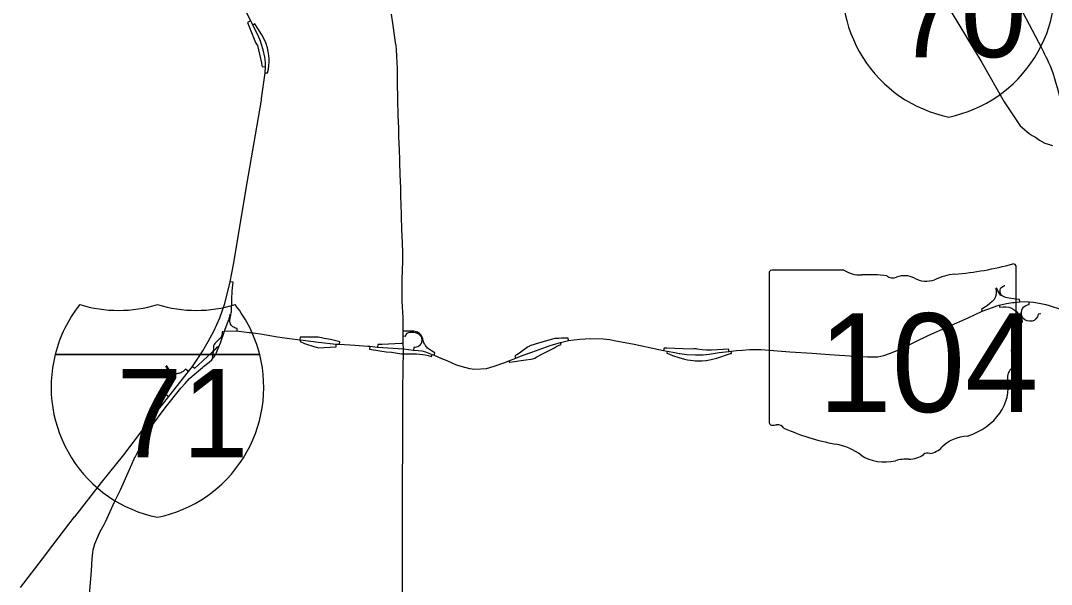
# Model space of a CAD drawing. Extents: x -7.1 to 34, y 0 to 22.
# Drawn here: x 5.239 to 6.584, y 16.034 to 16.769 of the extents above; entities that cross this region are included whole.
import ezdxf

# ---------------------------------------------------------------- set-up
doc = ezdxf.new("R2010")
doc.units = 0
for name, color, linetype in [('GM_X_Interchange_Ramps', 7, 'Continuous'), ('GM_X_Interstate_Route', 7, 'Continuous'), ('GM_X_Interstate_Shield', 7, 'Continuous'), ('GM_X_State_Route', 7, 'Continuous'), ('GM_X_State_Shield', 7, 'Continuous'), ('GM_X_US_Route', 7, 'Continuous')]:
    doc.layers.add(name, color=color, linetype=linetype)

msp = doc.modelspace()

# ---------------------------------------------------------------- linework, layer by layer
at = {"layer": 'GM_X_Interchange_Ramps'}
for points in [[(5.5389, 16.7691), (5.5349, 16.7671), (5.5453, 16.7407), (5.5467, 16.7386)], [(5.5594, 16.7384), (5.5585, 16.7403), (5.556, 16.7462), (5.5535, 16.7507), (5.5483, 16.7593), (5.5444, 16.7651), (5.5417, 16.7637)], [(5.5467, 16.7386), (5.5476, 16.7372), (5.553, 16.7145), (5.5536, 16.7108), (5.5537, 16.7093), (5.5584, 16.7095)], [(5.558, 16.7014), (5.561, 16.7011), (5.5621, 16.706), (5.5628, 16.7109), (5.5631, 16.7152), (5.5629, 16.7198), (5.5626, 16.7241), (5.5617, 16.7291), (5.5608, 16.7339), (5.5601, 16.7366), (5.5594, 16.7384)], [(5.5213, 16.3644), (5.5214, 16.3675), (5.5193, 16.3682), (5.5181, 16.3686), (5.5169, 16.3691), (5.5158, 16.3698), (5.5149, 16.3705), (5.514, 16.3714), (5.5135, 16.3719), (5.5127, 16.3731), (5.5124, 16.3739), (5.5121, 16.3749), (5.5119, 16.3759), (5.5118, 16.3769), (5.5119, 16.3783), (5.5121, 16.3801), (5.5127, 16.3835), (5.513, 16.3849), (5.5132, 16.3861), (5.5135, 16.388), (5.5137, 16.3895), (5.5138, 16.3904), (5.5143, 16.406), (5.5148, 16.4162), (5.5155, 16.4247), (5.5159, 16.4279), (5.5123, 16.4286)], [(6.5112, 16.4198), (6.5116, 16.4193), (6.5122, 16.416), (6.5122, 16.4135), (6.5117, 16.4107), (6.5106, 16.4082), (6.5092, 16.4055), (6.5068, 16.4028), (6.5036, 16.4), (6.5001, 16.3971), (6.4961, 16.3945), (6.4929, 16.3924), (6.4939, 16.39)], [(6.5186, 16.4109), (6.5182, 16.4105), (6.5171, 16.412), (6.5162, 16.4133), (6.5149, 16.4154), (6.5136, 16.4178), (6.5128, 16.4197), (6.5126, 16.4206)], [(6.543, 16.4023), (6.5426, 16.4053), (6.5347, 16.4063), (6.5288, 16.407), (6.5245, 16.4079), (6.5211, 16.4093), (6.5186, 16.4109), (6.5176, 16.4131), (6.5171, 16.4147), (6.5171, 16.4162), (6.5171, 16.418), (6.5177, 16.4196), (6.5183, 16.4205), (6.519, 16.4213), (6.5206, 16.4225), (6.5228, 16.4234), (6.5227, 16.4242)], [(6.5701, 16.3867), (6.5669, 16.3864), (6.5658, 16.3827), (6.5639, 16.3801), (6.5614, 16.378), (6.5589, 16.3772), (6.5557, 16.377), (6.5526, 16.3775), (6.5493, 16.379), (6.5468, 16.3812), (6.5455, 16.384), (6.5451, 16.3862), (6.5451, 16.3884), (6.5456, 16.3914), (6.5464, 16.3935), (6.5483, 16.3958), (6.5506, 16.3975), (6.5528, 16.3983), (6.5551, 16.3989), (6.5551, 16.4022)], [(6.516, 16.3981), (6.5168, 16.3953), (6.5211, 16.396), (6.5247, 16.396), (6.5284, 16.3956), (6.5312, 16.3946), (6.5343, 16.393), (6.5369, 16.3912), (6.539, 16.3892), (6.5409, 16.3865), (6.5424, 16.3834), (6.5435, 16.3798), (6.5439, 16.3769), (6.5439, 16.3754)], [(6.5463, 16.3752), (6.5463, 16.3769), (6.5459, 16.3788), (6.5455, 16.381), (6.545, 16.3835), (6.5446, 16.3863), (6.5445, 16.3885), (6.5451, 16.3884)], [(5.5047, 16.3643), (5.5056, 16.3668), (5.5091, 16.3758), (5.5097, 16.3773), (5.5102, 16.3786), (5.5107, 16.3799), (5.511, 16.3809), (5.5113, 16.382), (5.5117, 16.3835), (5.512, 16.3849), (5.5123, 16.3863), (5.5132, 16.3861)], [(5.5021, 16.3643), (5.5017, 16.362), (5.5016, 16.3609), (5.5012, 16.3588), (5.5008, 16.3576), (5.5003, 16.3564), (5.4995, 16.3551), (5.4984, 16.354), (5.4947, 16.3508), (5.4932, 16.3495), (5.4922, 16.3482), (5.4912, 16.3468), (5.4905, 16.3451), (5.4903, 16.3438), (5.4902, 16.3418), (5.4899, 16.3377), (5.4897, 16.3343), (5.4895, 16.3329), (5.489, 16.3313), (5.4886, 16.3305), (5.49, 16.3292)], [(5.7783, 16.3327), (5.7794, 16.3357), (5.7748, 16.3384), (5.7698, 16.342), (5.7687, 16.3432), (5.7679, 16.3441), (5.7672, 16.3452), (5.7665, 16.3462), (5.7659, 16.3473), (5.7652, 16.3485), (5.7647, 16.3498), (5.7643, 16.3509), (5.7638, 16.3524), (5.7634, 16.3542), (5.7631, 16.3555), (5.7625, 16.3571), (5.7616, 16.3587), (5.7606, 16.3599), (5.7593, 16.3612), (5.758, 16.362), (5.7565, 16.3628), (5.7553, 16.3632), (5.7536, 16.3636), (5.7518, 16.364), (5.7495, 16.3642), (5.7387, 16.3641), (5.7381, 16.3638)], [(5.7381, 16.3578), (5.7408, 16.3577), (5.7418, 16.3597), (5.7431, 16.3614), (5.7442, 16.362), (5.7453, 16.3624), (5.7466, 16.3627), (5.7483, 16.3628), (5.7501, 16.3628), (5.7517, 16.3627), (5.7534, 16.3624), (5.7547, 16.362), (5.7561, 16.3615), (5.7579, 16.3606), (5.7597, 16.359), (5.7606, 16.3578), (5.7613, 16.3566), (5.7619, 16.355), (5.7622, 16.3536), (5.7622, 16.3517), (5.7619, 16.35), (5.7613, 16.3482), (5.7606, 16.347), (5.7597, 16.3458), (5.7585, 16.3447), (5.7571, 16.3438), (5.7555, 16.3431), (5.7536, 16.3429), (5.7519, 16.3427), (5.7515, 16.3394)], [(5.6293, 16.3558), (5.6271, 16.3561), (5.6154, 16.3562), (5.6078, 16.3563), (5.6035, 16.3564), (5.603, 16.3529)], [(5.6038, 16.3528), (5.6035, 16.3504), (5.6091, 16.348), (5.6228, 16.3438), (5.625, 16.3431), (5.626, 16.3428)], [(5.655, 16.347), (5.6554, 16.3502), (5.6433, 16.353), (5.6377, 16.3541), (5.6347, 16.3547), (5.6312, 16.3555), (5.6293, 16.3558)], [(5.7381, 16.3479), (5.7352, 16.3478), (5.7106, 16.3468), (5.7047, 16.3465), (5.7045, 16.3433)], [(5.9538, 16.3517), (5.9534, 16.355), (5.9515, 16.355), (5.9445, 16.3549), (5.941, 16.3547), (5.9385, 16.3546), (5.9359, 16.3543), (5.9327, 16.3536), (5.9159, 16.3489), (5.9032, 16.345), (5.9025, 16.3441)], [(5.9099, 16.3288), (5.9117, 16.3303), (5.9196, 16.3345), (5.9347, 16.3421), (5.9384, 16.3446), (5.9417, 16.346), (5.944, 16.3468), (5.9434, 16.3493)], [(5.4628, 16.3181), (5.4662, 16.3156), (5.4708, 16.3201), (5.4759, 16.3249), (5.4897, 16.3376), (5.4899, 16.3377), (5.4916, 16.3393), (5.4932, 16.3412), (5.4959, 16.344), (5.4973, 16.3435)], [(5.626, 16.3428), (5.6276, 16.3424), (5.6349, 16.3428), (5.6428, 16.3432), (5.6503, 16.3436), (5.6506, 16.347)], [(5.6944, 16.3444), (5.6942, 16.3408), (5.7073, 16.3386), (5.7159, 16.3373), (5.7226, 16.3365), (5.7356, 16.3347), (5.7382, 16.3345)], [(5.7382, 16.3345), (5.7396, 16.3345), (5.7552, 16.3344), (5.7596, 16.3341), (5.7634, 16.3337), (5.7666, 16.333), (5.7705, 16.3322), (5.7749, 16.331), (5.7759, 16.3337)], [(5.9025, 16.3441), (5.9002, 16.3434), (5.8969, 16.3405), (5.8937, 16.3382), (5.8897, 16.3354), (5.8863, 16.3332), (5.8837, 16.3317), (5.8848, 16.329)], [(6.1202, 16.3409), (6.1173, 16.341), (6.1138, 16.3408), (6.082, 16.3418), (6.0785, 16.3421), (6.0785, 16.3421), (6.0779, 16.339)], [(6.0827, 16.3381), (6.0823, 16.3353), (6.0849, 16.3345), (6.0896, 16.3325), (6.0979, 16.3298), (6.1053, 16.3274), (6.109, 16.3267), (6.113, 16.3261), (6.1164, 16.3257), (6.119, 16.3254)], [(6.119, 16.3254), (6.121, 16.3252), (6.1248, 16.3254), (6.1282, 16.3254), (6.1335, 16.3258), (6.1401, 16.327), (6.1472, 16.329), (6.1654, 16.3348), (6.1664, 16.335), (6.1662, 16.3379)], [(6.1631, 16.3375), (6.1629, 16.3404), (6.1404, 16.3391), (6.1339, 16.3394), (6.1283, 16.3397), (6.1218, 16.3408), (6.1202, 16.3409)], [(5.8759, 16.3254), (5.8767, 16.3234), (5.877, 16.3235), (5.8981, 16.3266), (5.9047, 16.3275), (5.9072, 16.3279), (5.9099, 16.3288)], [(5.4277, 16.3181), (5.4286, 16.3171), (5.4309, 16.3132), (5.4313, 16.3122), (5.4319, 16.3107), (5.4324, 16.3091), (5.4327, 16.3079), (5.433, 16.3066), (5.4333, 16.3049), (5.4335, 16.3038), (5.4336, 16.3024), (5.4337, 16.301), (5.4337, 16.2992), (5.4337, 16.2979), (5.4336, 16.2965), (5.4334, 16.295), (5.4331, 16.2935), (5.4328, 16.292), (5.4324, 16.2906), (5.4319, 16.289), (5.4315, 16.2879), (5.4309, 16.2865), (5.4285, 16.2816), (5.4322, 16.2788)], [(5.4577, 16.3115), (5.4538, 16.3145), (5.4519, 16.3126), (5.4506, 16.3115), (5.4491, 16.3105), (5.4476, 16.3098), (5.4465, 16.3093), (5.4451, 16.3089), (5.444, 16.3087), (5.4427, 16.3086), (5.4417, 16.3086), (5.44, 16.3088), (5.4388, 16.3091), (5.4376, 16.3096), (5.4365, 16.3102), (5.4355, 16.3108), (5.4345, 16.3116), (5.4337, 16.3125), (5.4327, 16.3137), (5.4322, 16.3145), (5.4298, 16.3179), (5.4287, 16.319)]]:
    msp.add_lwpolyline(points, dxfattribs=at)
at = {"layer": 'GM_X_Interstate_Route'}
for points in [[(6.4124, 16.8819), (6.4125, 16.876), (6.4126, 16.8661), (6.414, 16.8573), (6.4162, 16.8482), (6.4184, 16.8432), (6.4196, 16.8403), (6.4214, 16.8365), (6.4243, 16.8304), (6.4333, 16.8144), (6.4935, 16.7147), (6.5223, 16.6633), (6.5434, 16.6322), (6.5549, 16.6221), (6.5591, 16.6194), (6.5633, 16.6172)], [(5.5403, 16.7664), (5.5389, 16.7691), (5.5328, 16.7809), (5.5148, 16.8168), (5.5043, 16.8364), (5.4919, 16.8623), (5.4919, 16.8665)], [(5.5529, 16.6657), (5.5532, 16.6678), (5.558, 16.7014), (5.5584, 16.7095), (5.5582, 16.7148), (5.5572, 16.7217), (5.5551, 16.7314), (5.5529, 16.7385), (5.5517, 16.7425), (5.5487, 16.7499), (5.5417, 16.7637), (5.5403, 16.7664)], [(5.4906, 16.3641), (5.4906, 16.3641), (5.4985, 16.3817), (5.5051, 16.4002), (5.5123, 16.4286), (5.5165, 16.4511), (5.5344, 16.5579), (5.5435, 16.6102), (5.5529, 16.6657)], [(6.5633, 16.6172), (6.5686, 16.6133), (6.5755, 16.6097), (6.5854, 16.6065)], [(5.3441, 16.1664), (5.3732, 16.2028), (5.4072, 16.2475), (5.4322, 16.2788), (5.4577, 16.3115), (5.4628, 16.3181), (5.4699, 16.3282), (5.4766, 16.3384), (5.4835, 16.3505), (5.4906, 16.3641)], [(5.3092, 16.1219), (5.3397, 16.1609), (5.3441, 16.1664)], [(5.2672, 16.0671), (5.2805, 16.0846), (5.3017, 16.1121), (5.309, 16.1216), (5.3092, 16.1219)], [(5.2386, 16.0295), (5.2672, 16.0671)]]:
    msp.add_lwpolyline(points, dxfattribs=at)
at = {"layer": 'GM_X_Interstate_Shield'}
for p, q in [((5.2837, 16.3337), (5.5507, 16.3337)), ((5.5507, 16.3337), (5.2837, 16.3337)), ((5.5507, 16.3337), (5.2837, 16.3337))]:
    msp.add_line(p, q, dxfattribs=at)
for centre, start, end in [((6.4848, 16.8136), 165.8066, 258.463), ((6.4154, 16.8136), 281.537, 14.1934), ((5.4519, 16.2911), 141.669, 165.8066), ((5.3665, 16.5647), 253.0091, 286.9909), ((5.4679, 16.5647), 253.0091, 286.9909), ((5.3825, 16.2911), 14.1934, 38.331), ((5.4519, 16.2911), 165.8066, 258.463), ((5.3825, 16.2911), 281.537, 14.1934)]:
    msp.add_arc(centre, 0.1735, start, end, dxfattribs=at)
at = {"layer": 'GM_X_State_Route'}
for points in [[(6.0984, 16.3351), (6.0992, 16.3349), (6.1082, 16.3338), (6.1197, 16.3332), (6.1294, 16.3334), (6.1374, 16.334), (6.1504, 16.3362), (6.1631, 16.3375), (6.1662, 16.3379), (6.173, 16.3387), (6.181, 16.3393), (6.1898, 16.34), (6.2054, 16.3402), (6.2427, 16.3371), (6.2718, 16.3352), (6.2944, 16.3335), (6.3273, 16.3314), (6.3439, 16.3304), (6.3497, 16.3305), (6.3577, 16.3307), (6.3652, 16.3324), (6.3739, 16.3353), (6.3859, 16.3401), (6.4242, 16.3588), (6.4754, 16.3814), (6.4939, 16.39), (6.507, 16.3951), (6.5128, 16.3972), (6.516, 16.3981), (6.5253, 16.4002), (6.5331, 16.4015), (6.5356, 16.4017)], [(6.5356, 16.4017), (6.543, 16.4023), (6.5493, 16.4026), (6.5551, 16.4022), (6.5607, 16.4018), (6.5681, 16.4006), (6.577, 16.3989), (6.581, 16.3978), (6.5852, 16.3965), (6.5935, 16.3937), (6.6044, 16.3893), (6.6159, 16.3836), (6.6241, 16.3802), (6.6393, 16.3744), (6.6552, 16.3697), (6.6676, 16.3675), (6.6795, 16.3662), (6.6837, 16.3658), (6.6841, 16.3656)], [(5.4773, 16.3178), (5.4845, 16.3235), (5.488, 16.3268), (5.49, 16.3292), (5.4912, 16.3308), (5.4932, 16.3341), (5.4952, 16.3383), (5.4973, 16.3435), (5.4993, 16.3488), (5.5047, 16.3643)], [(5.5047, 16.3643), (5.5047, 16.3643), (5.5213, 16.3644), (5.5233, 16.3642), (5.5369, 16.3624), (5.5385, 16.3622)], [(5.5385, 16.3622), (5.5518, 16.3604), (5.5738, 16.3569), (5.5895, 16.3546), (5.603, 16.3529), (5.6038, 16.3528), (5.6275, 16.3497), (5.6506, 16.347), (5.655, 16.347), (5.675, 16.3457), (5.6918, 16.3445)], [(5.9034, 16.3359), (5.9058, 16.3367), (5.9299, 16.3454), (5.9374, 16.3476), (5.9434, 16.3493), (5.9538, 16.3517), (5.9686, 16.3536), (5.9824, 16.3544), (5.9992, 16.354), (6.0076, 16.3531), (6.0133, 16.3519), (6.0393, 16.3472), (6.0779, 16.339), (6.0827, 16.3381), (6.0924, 16.3361), (6.0984, 16.3351)], [(5.6918, 16.3445), (5.6944, 16.3444), (5.7045, 16.3433), (5.7382, 16.3409)], [(5.7382, 16.3409), (5.7515, 16.3394), (5.7577, 16.3389), (5.7625, 16.3382), (5.7673, 16.3369), (5.7759, 16.3337), (5.7783, 16.3327), (5.788, 16.3284), (5.7948, 16.3257), (5.8014, 16.3227), (5.8064, 16.3205), (5.8131, 16.3182), (5.8246, 16.3152), (5.8316, 16.3143), (5.8466, 16.3154), (5.8567, 16.3184), (5.8707, 16.3232), (5.8759, 16.3254), (5.8848, 16.329), (5.8911, 16.3316), (5.9034, 16.3359)], [(5.398, 16.2192), (5.4041, 16.2314), (5.4086, 16.2386), (5.4273, 16.2642), (5.4478, 16.2897), (5.4532, 16.2957), (5.4592, 16.3021), (5.4651, 16.3075), (5.4761, 16.3168), (5.4773, 16.3178)], [(5.3879, 16.1996), (5.388, 16.1998), (5.3978, 16.2188), (5.398, 16.2192)], [(5.3493, 16.115), (5.3493, 16.115), (5.3617, 16.1423), (5.3691, 16.157), (5.3806, 16.1836), (5.3869, 16.1973), (5.3879, 16.1996)], [(5.331, 16.0516), (5.3321, 16.0669), (5.3329, 16.0752), (5.3335, 16.0787), (5.3343, 16.0819), (5.3355, 16.0864), (5.342, 16.1017), (5.3482, 16.1128), (5.3493, 16.115)], [(5.318, 15.9089), (5.3234, 15.9555), (5.3243, 15.9684), (5.3257, 15.983), (5.3273, 16.0063), (5.3294, 16.0302), (5.331, 16.0516), (5.331, 16.0516)]]:
    msp.add_lwpolyline(points, dxfattribs=at)
at = {"layer": 'GM_X_State_Shield'}
for p, q in [((6.3133, 16.4437), (6.219, 16.4437)), ((6.5379, 16.3463), (6.5379, 16.4486)), ((6.2158, 16.4404), (6.2158, 16.2448)), ((6.5379, 16.3463), (6.5379, 16.3463))]:
    msp.add_line(p, q, dxfattribs=at)
for centre, major_axis, start_param, end_param in [((6.2195, 16.4408), (0.00373, 0), 1.712693, 3.28349), ((6.3358, 16.4664), (0.0362, 0), 4.042523, 4.731795), ((6.4232, 16.7104), (0.3416, 0), 4.814394, 5.042369), ((6.5344, 16.449), (0.00359, 0), 6.141152, 7.989035), ((6.3478, 16.3339), (0.1299, 0), 1.404758, 1.657858), ((6.3773, 16.4418), (0.0104, 0), 3.836095, 5.185415), ((6.3926, 16.4192), (0.0217, 0), 0.950623, 2.079405), ((6.4207, 16.4502), (0.0261, 0), 4.081561, 5.145723), ((6.4668, 16.384), (0.0687, 0), 1.699011, 2.107814), ((6.5371, 16.3387), (0.00555, 0), 1.883978, 3.671073), ((6.5018, 16.3258), (0.0333, 0), 5.934695, 6.695948), ((6.5341, 16.3459), (0.00384, 0), 5.05454, 6.418171), ((6.5508, 16.3034), (0.0242, 0), 2.387724, 3.262537), ((6.4423, 16.2904), (0.0854, 0), 5.101752, 6.440018), ((6.2196, 16.2443), (0.00376, 0), 3.00124, 4.508301), ((6.2201, 16.2644), (0.0287, 0), 4.665946, 4.897461), ((6.226, 16.2335), (0.0104, 0), 0.519207, 1.627899), ((6.3568, 16.4092), (0.2467, 0), 4.195997, 4.488961), ((6.4784, 16.1899), (0.0468, 0), 1.647645, 2.488434), ((6.2833, 16.1569), (0.0772, 0), 0.823519, 1.323587), ((6.3667, 16.2325), (0.049, 0), 4.026481, 4.996735), ((6.3986, 16.2179), (0.0261, 0), 4.691044, 5.507374), ((6.4222, 16.1989), (0.00735, 0), 1.147584, 2.315152), ((6.4191, 16.2258), (0.0276, 0), 4.937069, 5.64225), ((6.395, 16.1649), (0.0402, 0), 1.495662, 1.94098)]:
    msp.add_ellipse(centre, major_axis=major_axis, ratio=0.8, start_param=start_param, end_param=end_param, dxfattribs=at)
at = {"layer": 'GM_X_US_Route'}
for points in [[(6.4963, 16.8762), (6.4969, 16.8749), (6.5035, 16.8621), (6.5088, 16.8523), (6.5139, 16.8427), (6.5211, 16.829), (6.5307, 16.8108), (6.5354, 16.8019), (6.5552, 16.7642), (6.5672, 16.7413), (6.5707, 16.7346), (6.5737, 16.7287), (6.5752, 16.7257)], [(5.7305, 16.6939), (5.7305, 16.7004), (5.7304, 16.707), (5.7297, 16.7226), (5.7293, 16.7317), (5.7287, 16.7368), (5.7281, 16.7409), (5.725, 16.7629), (5.7228, 16.7778)], [(6.5752, 16.7257), (6.577, 16.7223), (6.5793, 16.7175), (6.5795, 16.717)], [(6.5795, 16.717), (6.5805, 16.7148), (6.5824, 16.7103), (6.586, 16.7011), (6.5891, 16.6907), (6.5923, 16.6789), (6.5989, 16.652), (6.6016, 16.6424), (6.605, 16.6332), (6.607, 16.6283), (6.6105, 16.6211), (6.6146, 16.612), (6.6188, 16.6036)], [(5.7377, 16.4551), (5.7377, 16.4551), (5.7374, 16.4665), (5.737, 16.4798), (5.7363, 16.497), (5.7359, 16.5142), (5.7353, 16.5316), (5.7351, 16.5379), (5.7348, 16.5506), (5.734, 16.5685), (5.7336, 16.5847), (5.7335, 16.5877), (5.733, 16.6007), (5.7325, 16.6178), (5.7321, 16.6313), (5.7319, 16.6352), (5.7315, 16.6476), (5.731, 16.6643), (5.7306, 16.6916), (5.7305, 16.6939)], [(5.7366, 16.4215), (5.7365, 16.4314), (5.7377, 16.4551)], [(5.7367, 16.4071), (5.7366, 16.4215)], [(5.738, 16.371), (5.7379, 16.3738), (5.7379, 16.3814), (5.7368, 16.4034), (5.7368, 16.4063), (5.7367, 16.4071)], [(5.7382, 16.3409), (5.7381, 16.3479), (5.7381, 16.3531), (5.7381, 16.3578), (5.7381, 16.3638), (5.738, 16.371)], [(5.7379, 16.3182), (5.7382, 16.3345)], [(5.7382, 16.3345), (5.7382, 16.3409)], [(5.7203, 15.9331), (5.7275, 15.9542), (5.7338, 15.9735), (5.7353, 15.9806), (5.7362, 15.986), (5.7368, 15.992), (5.7371, 16.0028), (5.7369, 16.0924), (5.737, 16.1088), (5.737, 16.1233), (5.7371, 16.1393), (5.7371, 16.1575), (5.737, 16.1723), (5.737, 16.1758), (5.7371, 16.1836), (5.7373, 16.1979), (5.7376, 16.2243), (5.7375, 16.2294), (5.7377, 16.2572), (5.7377, 16.2722), (5.7377, 16.2881), (5.7379, 16.314), (5.7379, 16.3182)]]:
    msp.add_lwpolyline(points, dxfattribs=at)

# ---------------------------------------------------------------- texts
at = {"layer": 'GM_X_Interstate_Shield'}
for s, p in [('70', (6.3795, 16.7217)), ('71', (5.3637, 16.1992))]:
    msp.add_text(s, height=0.11569, dxfattribs=at).set_placement(p)
at = {"layer": 'GM_X_State_Shield'}
msp.add_text('104', height=0.12885, dxfattribs=at).set_placement((6.2798, 16.2586))

doc.saveas('drawing.dxf')
